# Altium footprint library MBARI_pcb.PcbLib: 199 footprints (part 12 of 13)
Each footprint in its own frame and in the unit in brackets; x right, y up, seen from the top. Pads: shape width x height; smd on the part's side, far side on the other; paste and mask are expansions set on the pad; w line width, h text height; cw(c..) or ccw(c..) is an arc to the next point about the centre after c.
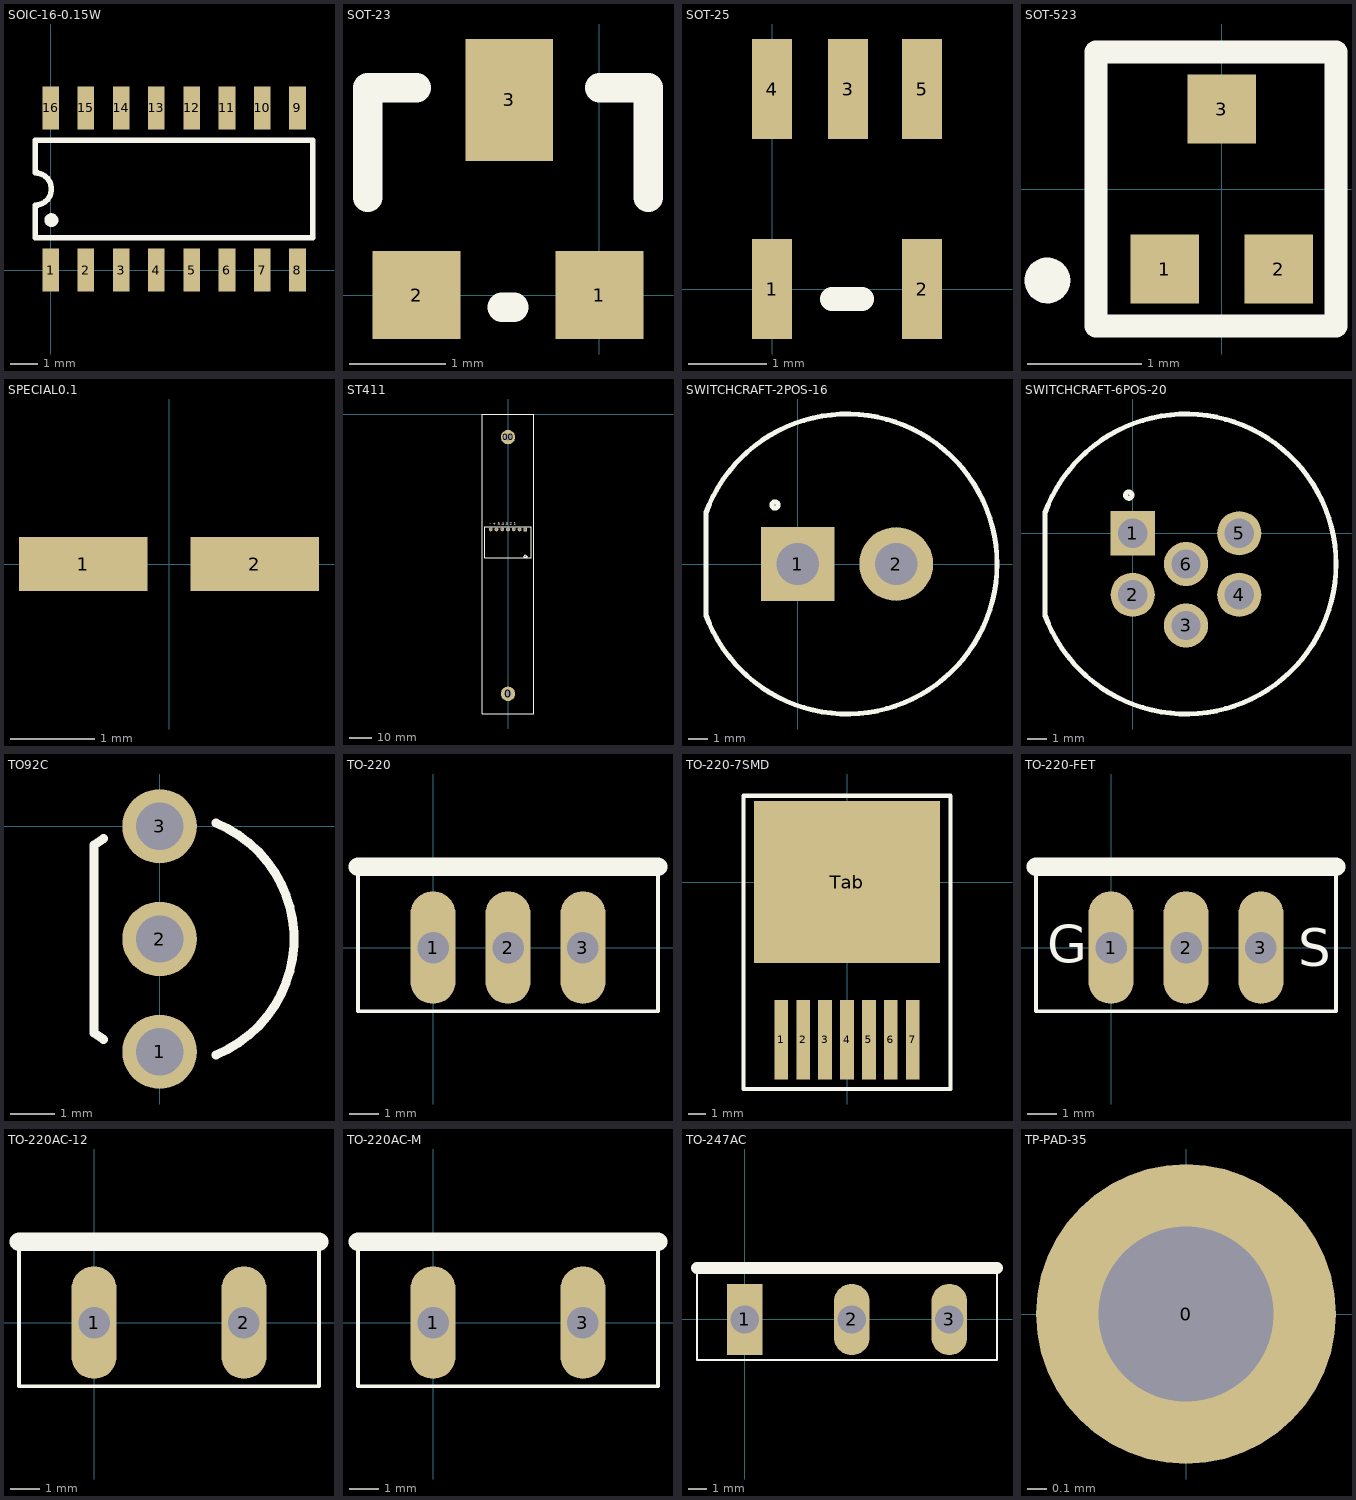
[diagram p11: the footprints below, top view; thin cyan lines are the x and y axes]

## SOIC-16-0.15W [mm] "SOIC-16 0.15\"Wide 1.27mm Pitch"
height 1.524
pads (16):
  rect 0.6x1.55 smd: 1(0,0) 2(1.27,0) 3(2.54,0) 4(3.81,0) 5(5.08,0) 6(6.35,0) 7(7.62,0) 8(8.89,0) 9(8.89,5.85) 10(7.62,5.85) 11(6.35,5.85) 12(5.08,5.85) 13(3.81,5.85) 14(2.54,5.85) 15(1.27,5.85) 16(0,5.85)
TopOverlay:
  circle w0.25: c0.027,1.803 r0.125
  lines w0.2: -0.555,1.175 9.445,1.175 9.445,4.675 -0.555,4.675 -0.555,3.508 cw(c-0.555,2.925) -0.555,2.342 -0.555,1.175

## SOT-23 [mil]
pads (3):
  rect 36x36 smd: 1(0,0) 2(-75,0)
  rect 36x50 smd: 3(-37,80)
TopOverlay:
  lines w12: -95,40 -95,85 -75,85 ; -40,-5 -35,-5 ; 0,85 20,85 20,40

## SOT-25 [mil]
pads (5):
  rect 20x50 smd: 1(0,0) 2(75,0) 3(38,100) 4(0,100) 5(75,100)
TopOverlay:
  lines w12: 30,-5 45,-5

## SOT-523 [mm] "Diodes Inc SOT-523"
pads (3):
  rect 0.6x0.6 smd: 1(-0.5,-0.7) 2(0.5,-0.7) 3(0,0.7)
TopOverlay:
  circle w0.2: c-1.525,-0.8 r0.1
  lines w0.2: -1.1,-1.2 1,-1.2 1,1.2 -1.1,1.2 -1.1,-1.2

## SPECIAL0.1 [mil]
pads (2):
  rect 60x25 smd: 1(-40,0) 2(40,0)

## ST411 [mil]
pads (9):
  round 250 hole 125: 0(0,-4850) 00(0,-400)
  rect 66x66 hole 42: 1(300,-2000)
  round 66 hole 42: 2(200,-2000) 3(100,-2000) 4(0,-2000) 5(-100,-2000) 6(-200,-2000) 7(-300,-2000)
TopOverlay:
  lines w10: -450,-5200 -450,-700 -450,0 450,0 450,-5200 -450,-5200 ; -400,-2490 -400,-1950 400,-1950 400,-2490 -400,-2490 ; 271.71,-2471.71 331.71,-2471.71 301.71,-2441.71 271.71,-2471.71
  text "- + 5 4 3 2 1" at -320,-1930 h51

## SWITCHCRAFT-2POS-16 [mil]
pads (2):
  rect 150x150 hole 86: 1(0,0)
  round 150 hole 86: 2(200,0)
TopOverlay:
  circle w10: c-46.4,120 r6.4
  lines w10: -186.61,-104.32 ccw(c100,0) -186.61,104.32 -186.61,-104.32

## SWITCHCRAFT-6POS-20 [mil]
pads (6):
  rect 90x90 hole 59.5: 1(0,0)
  round 90 hole 59.5: 2(0,-125) 3(108.25,-187.5) 4(216.51,-125) 5(216.51,0) 6(108.25,-62.5)
TopOverlay:
  circle w10: c-8.15,77.5 r6.4
  lines w10: -178.35,-166.82 ccw(c108.25,-62.5) -178.35,41.82 -178.35,-166.82

## TO92C [mil]
pads (3):
  round 66 hole 42: 1(0,-200) 2(0,-100) 3(0,0)
TopOverlay:
  lines w7.87: -49.71,-189.08 -58.33,-183.33 -58.33,-16.67 -49.71,-10.92 ; 49.85,-202.76 ccw(c8.33,-100) 49.85,2.76

## TO-220 [mil]
pads (3):
  oval 60x150 hole 42: 1(0,0) 2(100,0) 3(200,0)
TopOverlay:
  lines w5: -100,108 -100,-85 300,-85 300,108
  lines w25: -100,108 300,108

## TO-220-7SMD [mm] "TO-220 Surface Mount 7 leads"
height 4.4
pads (8):
  rect 0.8x4.6 smd: 1(-3.81,-9.14) 2(-2.54,-9.14) 3(-1.27,-9.14) 4(0,-9.14) 5(1.27,-9.14) 6(2.54,-9.14) 7(3.81,-9.14)
  rect 10.8x9.4 smd: Tab(0,0)
TopOverlay:
  lines w0.254: -6,-12 6,-12 6,5 -6,5 -6,-12

## TO-220-FET [mil]
pads (3):
  oval 60x150 hole 42: 1(0,0) 2(100,0) 3(200,0)
TopOverlay:
  lines w5: -100,108 -100,-85 300,-85 300,108
  lines w25: -100,108 300,108
  text "G" at -85,-20 h50
  text "S" at 250,-25 h50

## TO-220AC-12 [mil]
pads (2):
  oval 60x150 hole 42: 1(0,0) 2(200,0)
TopOverlay:
  lines w5: -100,108 -100,-85 300,-85 300,108
  lines w25: -100,108 300,108

## TO-220AC-M [mil]
pads (2):
  oval 60x150 hole 42: 1(0,0) 3(200,0)
TopOverlay:
  lines w5: -100,108 -100,-85 300,-85 300,108
  lines w25: -100,108 300,108

## TO-247AC [mil]
height 970
pads (3):
  rect 75x150 hole 59.5: 1(0,0)
  oval 75x150 hole 59.5: 2(225,0) 3(430,0)
TopOverlay:
  lines w5: -100,108 -100,-85 530,-85 530,108
  lines w25: -100,108 530,108

## TP-PAD-35 [mil] "TestPoint 35mil"
pads (1):
  round 60 hole 35: 0(0,0)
